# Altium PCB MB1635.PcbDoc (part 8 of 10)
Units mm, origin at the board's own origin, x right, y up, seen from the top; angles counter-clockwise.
Board outline 127 x 97 mm, 6 copper layers (Top Layer, Signal Layer 1, Signal Layer 2, Signal Layer 3, Signal Layer 4, Bottom Layer), stack 1.557 mm thick; 593 components, 478 nets, 2435 pads, 1743 vias.
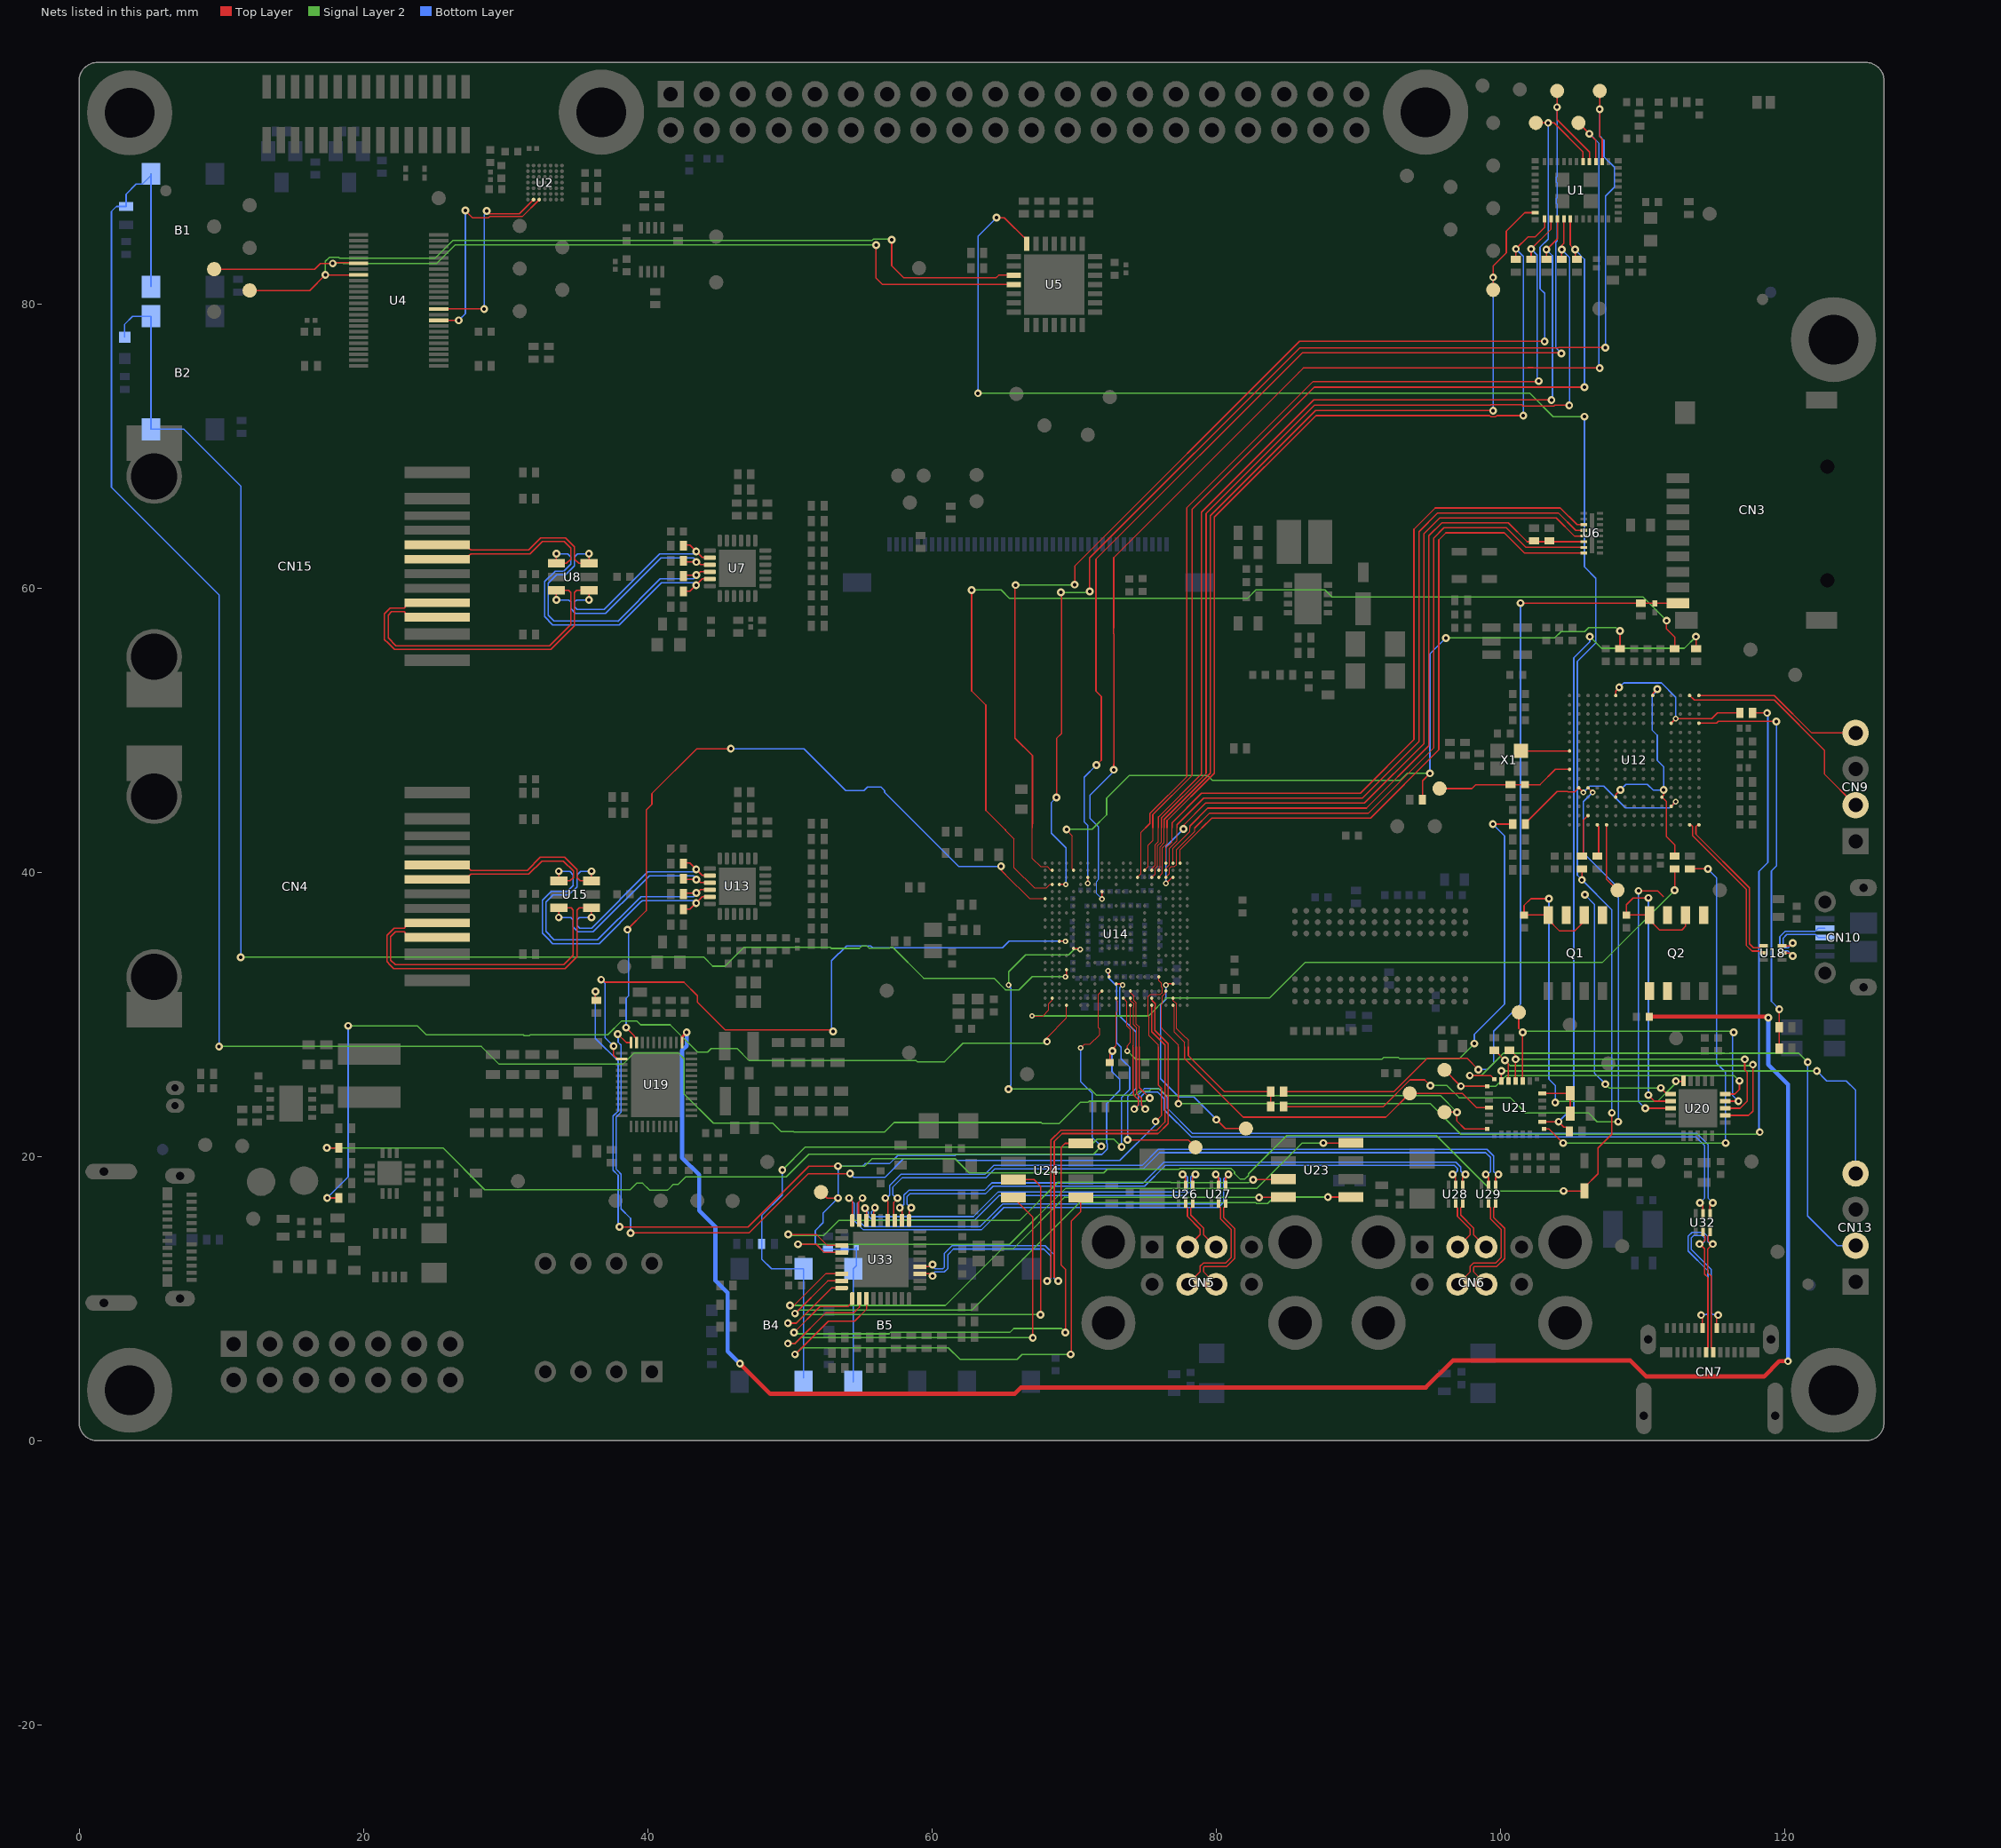
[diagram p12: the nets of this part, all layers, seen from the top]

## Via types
v1: diameter 0.55, hole 0.25, Top Layer to Bottom Layer, 1438 vias
v2: diameter 0.4, hole 0.2, Top Layer to Bottom Layer, 276 vias
v3: diameter 0.26, hole 0.1, Top Layer to Signal Layer 1, tented both sides, 29 vias

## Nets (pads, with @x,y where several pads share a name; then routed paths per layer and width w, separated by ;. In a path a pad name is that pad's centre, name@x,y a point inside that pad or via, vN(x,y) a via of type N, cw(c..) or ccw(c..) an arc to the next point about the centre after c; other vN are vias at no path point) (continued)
NetU2_E7: U2.E7 U4.33 | length 15.3
  Top Layer w0.1: U4.33@25.3,78.85 v1(26.7,78.85) ; v1(27.175,86.575) 27.675,86.075 28.801,86.075 28.876,86.15 31.175,86.15 U2.E7@32.375,87.35
  Bottom Layer w0.1: v1(26.7,78.85) 27.175,79.325 v1(27.175,86.575)
NetU2_F7: U2.F7 U4.35 | length 14
  Top Layer w0.1: U4.35@25.3,79.65 25.304,79.654 v1(28.501,79.654) ; v1(28.675,86.55) 28.875,86.35 30.975,86.35 U2.F7@31.975,87.35
  Bottom Layer w0.1: v1(28.501,79.654) 28.501,85.876 28.501,86.266 28.675,86.44 v1(28.675,86.55)
NetU12_G1: U12.G1 X1.3 | length 3.4
  Top Layer w0.1: X1.3@101.45,48.55 U12.G1@104.875,48.55
notOC1: U23.8 U33.13 | length 45.2
  Top Layer w0.1: v1(50.575,13.825) 51.875,13.825 52.45,13.25 U33.13@53.65,13.25 ; v1(87.55,20.95) 89.47,20.95 U23.8@89.475,20.955
  Signal Layer 2 w0.1: v1(50.575,13.825) 65.475,13.825 69.4,17.75 82.85,17.75 86.05,20.95 v1(87.55,20.95)
notOC2: U23.5 U33.17 | length 46.8
  Top Layer w0.1: v1(50.375,8.95) 52.675,11.25 U33.17@53.65,11.25 ; v1(87.875,17.15) 89.47,17.15 U23.5@89.475,17.145
  Signal Layer 2 w0.1: v1(50.375,8.95) 50.625,9.2 62.825,9.2 70.375,16.75 82.804,16.75 82.853,16.701 83.626,16.701 84.075,17.15 v1(87.875,17.15)
notOC3: U24.8 U33.19 | length 39.3
  Top Layer w0.1: v1(50.3,7.625) 52.125,9.45 54.1,9.45 54.4,9.75 U33.19@54.4,10 ; v1(69.4,7.625) 69.4,12.075 69.1,12.375 69.1,20.65 69.38,20.93 U24.8@70.475,20.93
  Signal Layer 2 w0.1: v1(50.3,7.625) 50.386,7.539 50.57,7.539 50.584,7.525 56.987,7.525 57.087,7.625 65.492,7.625 65.767,7.9 69.125,7.9 v1(69.4,7.625)
notOC4: U24.5 U33.21 | length 38.5
  Top Layer w0.1: v1(50.375,6.075) 52.725,8.425 54.575,8.425 55.4,9.25 U33.21@55.4,10 ; v1(69.775,6.075) 69.825,6.125 69.825,15.475 70.475,16.125 U24.5@70.475,17.12
  Signal Layer 2 w0.1: v1(50.375,6.075) 50.85,6.55 61.166,6.55 61.991,5.725 65.997,5.725 66.347,6.075 v1(69.775,6.075)
NRST: B5.1 B5.2 C118.1 C223.2 D4.2 R88.2 R114.1 R180.1 TP29.1 U5.14 U14.Y11 U37.1 | length 261.7
  Top Layer w0.075: 72.875,27.725 72.982,27.832 72.982,30.151 73.059,30.229 73.059,30.923 72.999,30.983 72.999,31.126 U14.Y11@72.975,31.15
  Top Layer w0.1: v1(36.325,31.625) 36.325,31.075 R114.1@36.4,31 ; v1(38.025,15.05) 47.075,15.05 51.35,19.325 v1(53.4,19.325) ; TP29.1@52.2,17.5 52.625,17.075 v1(53.4,17.075) ; v1(64.55,86.075) 65.1,86.075 66.675,84.5 U5.14@66.675,84.225 ; C118.1@72.525,26.625 72.525,27.325 72.626,27.426 v1(72.703,27.426) ; v1@72.675,27.525 72.875,27.725 ; v1(104.45,17.575) 105.92,17.575 105.92,17.845 106.875,18.8 106.875,20.6 107.85,21.575 v1(107.85,23.075) ; v1(105.75,39.475) R88.2@105.75,40.25
  Signal Layer 2 w0.1: v1(53.4,19.325) 55.275,19.325 55.8,19.85 61.625,19.85 62.625,18.85 72.1,18.85 72.35,19.1 77.399,19.1 77.474,19.175 81.051,19.175 81.3,18.926 81.3,18.804 81.678,18.426 82.03,18.426 82.279,18.675 82.279,18.784 84.97,21.475 95.5,21.475 99.4,17.575 v1(104.45,17.575) ; v1(63.25,73.725) 102.075,73.725 103.725,72.075 v1(105.925,72.075)
  Bottom Layer w0.1: v1(36.325,31.625) 36.325,28.325 37.925,26.725 37.925,23.2 ; 37.925,23.75 37.925,23.2 ; v1(38.025,15.05) 37.939,15.136 37.939,15.32 37.925,15.334 37.925,18.685 37.575,19.035 37.575,22.85 37.925,23.2 ; B5.2@54.475,4.15 B5.1@54.475,12.1 54.692,12.317 U37.1@54.692,13.602 ; U37.1@54.692,13.625 U37.1@54.692,13.602 ; v1(63.25,73.725) 63.25,84.775 v1(64.55,86.075) ; v1@72.675,27.525 72.675,25.975 73.225,25.425 73.225,24.658 72.3,23.733 72.3,20.951 72.35,20.901 72.35,20.549 72.3,20.499 72.3,20.475 71.975,20.15 61.725,20.15 61.65,20.075 57.6,20.075 57.025,19.5 55.3,19.5 55.125,19.325 v1(53.4,19.325) v1(53.4,17.075) 52.349,16.024 52.349,15.349 51.8,14.8 51.8,13.9 52.213,13.487 R180.1@52.692,13.487 C223.2@53.867,13.487 54.577,13.487 U37.1@54.692,13.602 ; v1(105.925,72.075) 105.925,61.5 106.725,60.7 106.725,56.15 105.422,54.847 105.422,39.803 v1(105.75,39.475) 107.85,37.375 v1(107.85,23.075)
PA13: B2.1 B2.2 LD4.2 U14.T4 | length 113.2
  Top Layer w0.09: v2@69.475,32.725 U14.T4@69.475,33.15
  Signal Layer 2 w0.09: 65.175,31.75 65.2,31.725 66.125,31.725 67.05,32.65 v2(69.4,32.65)
  Signal Layer 2 w0.1: v1(11.375,34.025) 11.4,34.05 43.934,34.05 44.584,33.4 45.449,33.4 46.774,34.725 52.849,34.725 52.924,34.65 54.9,34.65 55.077,34.827 55.429,34.827 55.579,34.677 57.029,34.677 57.077,34.725 57.25,34.725 59.425,32.55 64.375,32.55 65.175,31.75
  Bottom Layer w0.1: LD4.2@3.205,77.663 3.205,78.58 3.763,79.138 B2.1@5.055,79.138 B2.2@5.055,71.188 7.372,71.188 11.375,67.185 v1(11.375,34.025)
PA14: B1.1 B1.2 LD3.2 U14.W13 | length 153.4
  Top Layer w0.075: U14.W13@73.975,31.65 73.998,31.627 73.998,31.502 74.225,31.275 74.225,30.987 74.39,30.822 74.39,29.335 74.595,29.13 74.595,27.725
  Top Layer w0.1: 74.595,27.725 74.595,27.269 74.595,24.855 v1(75.325,24.125)
  Signal Layer 2 w0.1: v1(9.85,27.75) 28.3,27.75 29.55,26.5 38.275,26.5 39.075,27.3 42.151,27.3 42.575,26.876 42.575,24.401 44.626,22.35 48.804,22.35 49.404,21.75 50.284,21.75 50.309,21.725 56.675,21.725 57.35,22.4 67.7,22.4 67.775,22.325 68.95,22.325 70.451,23.826 70.979,23.826 71.053,23.9 75.041,23.9 75.266,24.125 v1(75.325,24.125)
  Bottom Layer w0.1: B1.2@5.055,81.213 B1.1@5.055,89.038 ; B1.1@5.055,89.163 B1.1@5.055,89.038 ; v1(9.85,27.75) 9.85,59.525 2.275,67.1 2.275,86.517 2.621,86.863 LD3.2@3.305,86.863 3.305,87.73 4.013,88.438 4.455,88.438 B1.1@5.055,89.038
PF8_WKUP: U14.F1 U19.43 | length 52.5
  Top Layer w0.075: 65.175,39.85 66.875,38.15 U14.F1@67.975,38.15
  Top Layer w0.1: v1(38.487,29.075) 39.075,28.487 39.075,28.424 39.149,28.35 39.212,28.35 39.225,28.337 U19.43@39.225,28.025 ; v1(38.575,35.975) 39.9,37.3 39.9,44.383 40.3,44.783 40.3,45.55 43.452,48.702 v1(45.852,48.702) ; v1(64.875,40.425) 64.875,40.15 65.175,39.85
  Bottom Layer w0.1: v1(38.487,29.075) 38.487,31.137 38.65,31.3 38.65,35.9 v1(38.575,35.975) ; v1(45.852,48.702) 50.998,48.702 53.95,45.75 55.225,45.75 55.475,46 56.426,46 56.675,45.751 56.675,45.625 61.875,40.425 v1(64.875,40.425)
PH4: R188.2 R189.2 U14.Y19 | length 12.4
  Top Layer w0.075: U14.Y19@76.975,31.15 76.986,31.139 76.986,30.989 77.225,30.75 77.225,30.296 77.225,29.025 77.638,28.613 78.05,28.2 78.05,27.725
  Top Layer w0.1: 78.05,27.725 78.05,27.1 80.582,24.568 R188.2@83.85,24.568 R189.2@83.85,23.518
PMIC_WAKEUP: U14.M3 U19.2 | length 47.1
  Top Layer w0.09: v1(37.6,27.775) 37.6,27.145 37.87,26.875 U19.2@38.175,26.875 ; U14.M3@68.975,35.15 v2(69.4,35.15) v2@69.425,35.15
  Top Layer w0.1: v1(36.725,32.45) 36.834,32.45 37.009,32.275 42.551,32.275 43.5,31.326 43.5,30.875 45.45,28.925 52.925,28.925 v1(53.05,28.8)
  Bottom Layer w0.09: 52.95,33.725 52.95,33.775 53.997,34.822 55.703,34.822 55.843,34.682 64.985,34.682 65.175,34.872 65.453,35.15 v2(69.4,35.15)
  Bottom Layer w0.1: v1(36.725,32.45) 37,32.175 37,28.375 v1(37.6,27.775) ; 52.95,33.725 52.95,29.084 52.964,29.07 52.964,28.886 v1(53.05,28.8)
PRTPWR1: U23.3 U33.12 | length 40.6
  Top Layer w0.1: v1(49.9,14.525) 49.925,14.5 51.9,14.5 52.65,13.75 U33.12@53.65,13.75 ; v1(82.604,18.376) 84.666,18.376 84.715,18.425 U23.3@84.725,18.415
  Signal Layer 2 w0.1: v1(49.9,14.525) 49.975,14.45 52.4,14.45 53.45,15.5 66.175,15.5 68.875,18.2 76.778,18.2 76.803,18.176 82.326,18.176 82.526,18.376 v1(82.604,18.376)
PRTPWR2: U23.4 U33.16 | length 42.4
  Top Layer w0.1: v1(50.025,9.525) 50.3,9.525 52.525,11.75 U33.16@53.65,11.75 ; v1(83.029,17.126) 84.696,17.126 84.72,17.15 U23.4@84.725,17.145
  Signal Layer 2 w0.1: v1(50.025,9.525) 60.95,9.525 64.925,13.5 65.7,13.5 69.35,17.15 69.374,17.126 v1(83.029,17.126)
PRTPWR3: U24.3 U33.18 | length 34
  Top Layer w0.1: v1(49.875,8.275) 50.475,8.275 52.95,10.75 U33.18@53.65,10.75 ; U24.3@65.725,18.39 67.185,18.39 67.65,17.925 v1(67.65,8.875)
  Signal Layer 2 w0.1: v1(49.875,8.275) 50.425,8.275 51.025,8.875 v1(67.65,8.875)
PRTPWR4: U24.4 U33.20 | length 34.5
  Top Layer w0.1: v1(49.875,6.85) 50.375,6.85 52.525,9 54.5,9 54.9,9.4 U33.20@54.9,10 ; U24.4@65.725,17.12 67.1,15.745 v1(67.1,7.25)
  Signal Layer 2 w0.1: v1(49.875,6.85) 50.375,6.85 50.775,7.25 v1(67.1,7.25)
PWR_LP: TP61.1 U14.V19 | length 15
  Top Layer w0.09: v2@76.55,32.15 U14.V19@76.975,32.15
  Top Layer w0.1: v1(80.025,22.6) 80.65,21.975 TP61.1@82.1,21.975 TP61.1@82.475,21.975
  Bottom Layer w0.09: 76.1,27.725 76.1,30.7 76.475,31.075 v2(76.475,32.075)
  Bottom Layer w0.1: 76.1,27.725 76.1,25.47 77.379,24.191 78.434,24.191 v1(80.025,22.6)
PWR_NJTRST: TP63.1 U14.V11 | length 17.5
  Top Layer w0.1: U14.V11@72.975,32.15 v2@73.4,32.15 ; v1(73.775,21.175) 78.025,21.175 TP63.1@78.55,20.65 TP63.1@78.55,20.3
  Bottom Layer w0.09: v2(73.425,32.075) 73.225,31.875 73.225,29.9 74.375,28.75 74.375,27.725
  Bottom Layer w0.1: v1(73.775,21.175) 73.775,24.2 74.375,24.8 74.375,27.725
PWR_ON: U14.U17 U19.44 | length 68.4
  Top Layer w0.075: 75.95,27.725 75.95,27.85 75.284,28.516 75.284,29.816 75.221,29.879 75.221,31.246 75.378,31.403 76.076,31.403 76.225,31.552 76.225,31.856 76.144,31.938 76.144,32.206 75.974,32.376 U14.U17@75.974,32.65
  Top Layer w0.1: v1(37.9,28.625) 38.5,28.025 U19.44@38.825,28.025 ; v1(38.8,14.625) 47.125,14.625 51.3,18.8 v1(54.25,18.8) ; v1(75.75,22.475) 76.15,22.875 76.15,24.816 75.95,25.016 75.95,27.725
  Bottom Layer w0.1: v1(37.9,28.625) 37.925,28.6 37.925,28.051 38.125,27.851 38.125,23.4 ; 38.125,23.165 38.125,23.117 ; 38.125,23.579 38.125,23.4 ; v1(38.8,14.625) 38.8,15.65 38.125,16.325 38.125,18.768 37.891,19.002 37.775,19.118 37.775,22.767 38.125,23.117 ; v1(54.25,18.8) 54.5,18.55 56.7,18.55 58,19.85 61.625,19.85 61.75,19.725 73.225,19.725 75.75,22.25 v1(75.75,22.475) ; 38.125,23.117 38.125,23.4
PWR_ON_DB: C102.2 Q2.5 Q2.6 U19.35 | length 135.7
  Top Layer w0.2: U19.35@42.425,28.025 42.425,28.425 v1(42.75,28.75)
  Top Layer w0.3: v1(46.5,5.425) 48.625,3.3 65.825,3.3 66.275,3.75 94.763,3.75 96.663,5.65 107.16,5.65 109.15,5.65 110.275,4.525 118.55,4.525 119.625,5.6 v1(120.244,5.6) ; C102.2@110.475,29.85 118.707,29.85 118.782,29.775 v1(118.85,29.775)
  Bottom Layer w0.3: v1(42.75,28.75) 42.75,27.801 42.425,27.476 42.425,19.925 43.625,18.725 43.625,16.2 44.775,15.05 44.775,11.275 45.625,10.425 45.625,6.3 v1(46.5,5.425) ; v1(118.85,29.775) 118.85,26.475 120.244,25.081 v1(120.244,5.6)
RD1_N: CN4.8 R97.1 U13.22 U15.6 | length 34
  Top Layer w0.09: CN4.8@25.2,40.53 27.195,40.53 27.58,40.145 29.93,40.145 31.531,40.145 32.446,41.06 34.169,41.06 35.025,40.204 35.025,39.625 35.25,39.4 U15.6@36.05,39.4 v1(36.05,40.075) ; R97.1@42.525,38.475 42.6,38.55 v1(43.425,38.55) 43.5,38.55 43.725,38.775 U13.22@44.375,38.775
  Bottom Layer w0.09: v1(36.05,40.075) 35.275,40.075 35.025,39.825 35.025,39.218 35.035,39.208 35.035,38.992 34.443,38.4 33.339,38.4 32.864,37.925 32.85,37.925 32.85,35.839 33.425,35.264 33.425,35.25 36.486,35.25 39.444,38.208 39.458,38.208 39.531,38.281 43.231,38.281 43.425,38.475 v1(43.425,38.55)
RD1_P: CN4.7 R99.1 U13.23 U15.1 | length 34.1
  Top Layer w0.09: CN4.7@25.2,39.51 27.195,39.51 27.57,39.885 29.822,39.885 31.639,39.885 32.554,40.8 34.075,40.8 34.775,40.1 34.775,39.625 34.55,39.4 U15.1@33.75,39.4 v1(33.75,40.075) ; R99.1@42.525,37.4 42.975,37.4 v1(43.413,37.838) 43.85,38.275 U13.23@44.375,38.275
  Bottom Layer w0.09: v1(33.75,40.075) 34.525,40.075 34.765,39.835 34.765,39.11 34.775,39.1 34.335,38.66 33.231,38.66 32.756,38.185 32.742,38.185 32.59,38.033 32.59,35.731 33.165,35.156 33.165,35.142 33.317,34.99 36.594,34.99 39.552,37.948 39.566,37.948 39.639,38.021 43.229,38.021 v1(43.413,37.838)
RD2_N: CN15.8 R40.1 U7.22 U8.6 | length 33.5
  Top Layer w0.09: CN15.8@25.2,63.06 27.195,63.06 27.455,62.8 27.455,62.795 27.565,62.685 31.621,62.685 32.486,63.55 34.229,63.55 34.85,62.929 34.85,62.05 35.15,61.75 U8.6@35.875,61.75 v1(35.875,62.425) ; R40.1@42.525,60.85 42.6,60.925 v1(43.425,60.925) 43.5,60.925 43.725,61.15 U7.22@44.375,61.15
  Bottom Layer w0.09: v1(35.875,62.425) 35.075,62.425 34.86,62.21 34.86,61.581 34.385,61.106 34.385,61.092 34.233,60.94 33.61,60.94 33.6,60.95 33.01,60.36 33.01,58.11 33,58.1 33.415,57.685 37.89,57.685 37.9,57.675 40.881,60.656 43.231,60.656 43.425,60.85 v1(43.425,60.925)
RD2_P: CN15.7 R42.1 U7.23 U8.1 | length 33.6
  Top Layer w0.09: CN15.7@25.2,62.04 27.195,62.04 27.455,62.3 27.455,62.305 27.575,62.425 31.729,62.425 32.604,63.3 34.125,63.3 34.225,63.2 34.6,62.825 34.6,62.05 34.3,61.75 U8.1@33.575,61.75 v1(33.575,62.425) ; R42.1@42.525,59.775 42.975,59.775 v1(43.413,60.213) 43.85,60.65 U7.23@44.375,60.65
  Bottom Layer w0.09: v1(33.575,62.425) 34.375,62.425 34.6,62.2 34.6,61.689 34.125,61.214 34.125,61.2 33.718,61.2 33.708,61.21 33.492,61.21 32.75,60.468 32.75,58.218 32.74,58.208 32.74,57.992 33.307,57.425 37.782,57.425 37.792,57.415 38.008,57.415 40.989,60.396 43.229,60.396 v1(43.413,60.213)
SDMMC1_CK: R33.2 R34.1 U6.6 U14.A19 | length 48.9
  Top Layer w0.075: U14.A19@76.975,40.65 76.975,41.7 78.15,42.875 78.15,43.125
  Top Layer w0.1: 78.15,43.125 78.15,43.265 79.41,44.525 90.585,44.525 94.975,48.915 94.975,63.69 95.885,64.6 100.565,64.6 101.89,63.275 102.375,63.275 103.45,63.275 U6.6@105.875,63.275
SDMMC1_CMD: U6.5 U14.C19 | length 51.8
  Top Layer w0.09: v1(77.7,43.05) v1@77.7,43.125
  Top Layer w0.1: v2(76.475,39.225) 76.875,39.625 76.95,39.625 76.975,39.65 U14.C19@76.975,39.638 ; v1@77.7,43.125 77.7,43.31 79.265,44.875 90.275,44.875 ; U6.5@105.875,63.675 105.21,63.675 103.935,64.95 95.74,64.95 94.625,63.835 94.625,49.06 90.44,44.875 ; 90.275,44.875 90.44,44.875 ; 90.275,44.875 90.44,44.875
  Bottom Layer w0.09: v2(76.475,39.225) 76.475,41.825 v1(77.7,43.05)
SDMMC1_D0: U6.7 U14.C18 | length 49.8
  Top Layer w0.075: U14.C18@76.475,39.65 76.725,39.9 76.725,40.275 76.85,40.4 77.079,40.4 77.225,40.546 77.225,41.605 78.505,42.885 78.505,43.125
  Top Layer w0.1: 78.505,43.125 79.555,44.175 90.73,44.175 95.325,48.77 95.325,63.545 96.03,64.25 100.42,64.25 101.795,62.875 U6.7@105.875,62.875
SDMMC1_D1: U6.8 U14.A20 | length 47.8
  Top Layer w0.075: U14.A20@77.475,40.65 77.475,41.6 79,43.125
  Top Layer w0.1: 79,43.125 79.7,43.825 90.875,43.825 95.675,48.625 95.675,63.4 96.175,63.9 100.275,63.9 101.7,62.475 U6.8@105.875,62.475
SDMMC1_D2: U6.3 U14.A18 | length 50.3
  Top Layer w0.075: U14.A18@76.475,40.65 76.475,41.716 76.9,42.141 76.9,43.125
  Top Layer w0.1: 76.9,43.125 76.9,43.5 78.975,45.575 90.15,45.575 93.925,49.35 93.925,64.15 95.425,65.65 104.225,65.65 105.4,64.475 U6.3@105.875,64.475
SDMMC1_D3: U6.4 U14.B18 | length 50.4
  Top Layer w0.075: U14.B18@76.475,40.15 76.475,40.296 76.725,40.546 76.725,41.705 77.25,42.23 77.25,43.125
  Top Layer w0.1: 77.25,43.125 77.25,43.355 79.12,45.225 90.295,45.225 94.275,49.205 94.275,63.98 95.595,65.3 104.08,65.3 105.305,64.075 U6.4@105.875,64.075
SDMMC2_CK: TP27.1 U1.20 U14.B17 | length 65.9
  Top Layer w0.075: U14.B17@75.975,40.15 75.987,40.162 75.987,40.309 76.059,40.381 76.059,41.798 76.35,42.089 76.35,43.125
  Top Layer w0.1: 76.35,43.125 76.35,43.733 79.6,46.983 79.6,65.1 87,72.5 v1(99.5,72.5) ; TP27.1@99.5,81 v1(99.5,81.875) 99.5,82.675 100.425,83.6 100.425,85.125 101.725,86.425 U1.20@102.45,86.425
  Bottom Layer w0.1: v1(99.5,72.5) v1(99.5,81.875)
SDMMC2_CMD: R14.2 U1.22 U14.C17 | length 67.6
  Top Layer w0.075: U14.C17@75.975,39.65 75.975,39.678 76.228,39.931 76.228,40.311 76.228,41.728 76.55,42.05 76.55,42.35 76.55,43.125
  Top Layer w0.1: 76.55,43.125 76.55,43.65 79.875,46.975 79.875,65 87.025,72.15 99.249,72.15 99.324,72.075 99.676,72.075 99.751,72.15 v1(101.625,72.15) ; R14.2@101.1,83.15 v1(101.1,83.875) 101.95,84.725 102.45,84.725 103.125,85.4 U1.22@103.125,85.975
  Bottom Layer w0.1: v1(101.1,83.875) 101.625,83.35 v1(101.625,72.15)
SDMMC2_D0: R16.2 U1.24 U14.B16 | length 68.5
  Top Layer w0.075: U14.B16@75.475,40.15 75.498,40.173 75.498,40.298 75.721,40.521 75.721,41.521 75.721,41.938 75.95,42.167 75.95,43.125
  Top Layer w0.1: 75.95,43.125 75.95,43.9 78.975,46.925 78.975,65.35 86.875,73.25 v1(103.6,73.25) ; R16.2@103.25,83.15 v1(103.25,83.825) 104.025,84.6 U1.24@104.025,85.975
  Bottom Layer w0.1: v1(103.25,83.825) 103.675,83.4 103.675,73.325 v1(103.6,73.25)
SDMMC2_D1: R18.2 U1.26 U14.B15 | length 71
  Top Layer w0.075: U14.B15@74.975,40.15 75.225,40.4 75.225,41.025 75.225,41.92 75.557,42.252 75.557,43.118 75.55,43.125
  Top Layer w0.1: 75.55,43.125 75.55,44.066 78.325,46.841 78.325,65.575 86.9,74.15 v1(105.925,74.15) ; U1.26@104.925,85.975 104.925,84.15 105.25,83.825 v1(105.275,83.825) 105.275,83.275 R18.2@105.4,83.15
  Bottom Layer w0.1: v1(105.275,83.825) 105.275,83.8 105.925,83.15 v1(105.925,74.15)
SDMMC2_D2: R15.2 U1.23 U14.C14 | length 68.8
  Top Layer w0.075: U14.C14@74.475,39.65 74.725,39.9 74.725,42.817 75.038,43.13
  Top Layer w0.1: 75.038,43.13 75.35,43.442 75.35,44.149 77.95,46.749 77.95,65.675 86.825,74.55 102.675,74.55 v1(102.7,74.575) ; R15.2@102.175,83.15 v1(102.175,83.875) 103.575,85.275 U1.23@103.575,85.975
  Bottom Layer w0.1: v1(102.175,83.875) 102.6,83.45 102.6,74.797 102.7,74.697 v1(102.7,74.575)
SDMMC2_D3: R17.2 U1.25 U14.C16 | length 70.1
  Top Layer w0.075: U14.C16@75.475,39.65 75.721,39.896 75.721,40.282 75.89,40.451 75.89,41.69 75.89,41.868 76.15,42.128 76.15,43.125
  Top Layer w0.1: 76.15,43.125 76.15,43.816 79.3,46.966 79.3,65.25 86.925,72.875 99.274,72.875 99.324,72.925 101.5,72.925 101.6,72.825 103.776,72.825 103.826,72.875 v1(104.85,72.875) ; R17.2@104.325,83.15 v1(104.325,83.825) 104.325,84.125 104.475,84.275 U1.25@104.475,85.975
  Bottom Layer w0.1: v1(104.325,83.825) 104.875,83.275 104.875,72.9 v1(104.85,72.875)
SNK_GDCG: C87.1 Q2.2 Q2.4 U20.7 | length 23.8
  Top Layer w0.1: v1(110.425,24.325) 110.85,23.9 U20.7@111.975,23.9 ; v1(110.425,38.2) 109.35,38.2 108.875,37.725 C87.1@108.875,37 Q2.4@110.495,37 110.495,36.655 111.2,35.95 112.775,35.95 113.035,36.21 Q2.2@113.035,37
  Bottom Layer w0.1: v1(110.425,24.325) v1(110.425,38.2)
SNK_GDCS: Q2.1 Q2.3 U20.8 | length 19.2
  Top Layer w0.1: v1(109.725,38.7) 111.075,38.7 111.475,38.3 ; v1(110.2,23.4) U20.8@111.975,23.4
  Bottom Layer w0.1: v1(109.725,38.7) 109.725,23.875 v1(110.2,23.4)
SRC_GDCG: C86.1 Q1.2 Q1.4 U20.5 | length 32.5
  Top Layer w0.1: v1(103.425,38.15) 102.15,38.15 101.675,37.675 C86.1@101.675,37 Q1.4@103.37,37 103.37,36.68 104.175,35.875 105.225,35.875 105.91,36.56 Q1.2@105.91,37 ; v1(112.35,25.3) 112.875,25.3 U20.5@112.9,25.325
  Signal Layer 2 w0.1: v1(103.875,23.8) 103.95,23.875 111.05,23.875 112.212,25.037 112.212,25.04 112.35,25.178 v1(112.35,25.3)
  Bottom Layer w0.1: v1(103.425,38.15) 103.425,25.45 103.875,25 v1(103.875,23.8)
SRC_GDCS: Q1.1 Q1.3 U20.6 | length 18.8
  Top Layer w0.1: v1(111.3,24.825) 111.725,24.4 U20.6@111.975,24.4
  Signal Layer 2 w0.1: v1(107.4,25.1) 107.675,24.825 v1(111.3,24.825)
  Bottom Layer w0.1: v1(105.95,38.425) 106.625,37.75 106.625,25.875 v1(107.4,25.1)
STLINK_SWCLK: R90.2 U14.Y2 | length 52.7
  Top Layer w0.075: v2(67.05,29.9) 67.8,29.9 68.225,30.325 68.225,30.76 68.475,31.01 U14.Y2@68.475,31.15
  Top Layer w0.1: v1(112.275,38.75) R90.2@112.275,40.25
  Signal Layer 2 w0.1: v2(67.05,29.9) 75.25,29.9 76.525,31.175 81.275,31.175 83.775,31.175 86.275,33.675 107.2,33.675 v1(112.275,38.75)
STLINK_SWDIO: R81.2 U14.Y12 | length 47.3
  Top Layer w0.075: U14.Y12@73.475,31.15 73.725,30.9 73.725,29.194 73.982,28.938 73.982,28.032 73.75,27.8 73.75,27.725
  Top Layer w0.1: v2(73.75,27.425) 73.75,27.725 ; v1(99.475,43.4) R81.2@100.875,43.4
  Signal Layer 2 w0.1: v2(73.75,27.425) 73.775,27.425 74.35,26.85 91.674,26.85 91.799,26.975 92.826,26.975 92.926,26.875 97.1,26.875 v1(98.175,27.95)
  Bottom Layer w0.1: v1(98.175,27.95) 98.175,28.6 100.3,30.725 100.3,42.575 v1(99.475,43.4)
STLINK_SWO: R61.2 U14.W18 | length 81.2
  Top Layer w0.075: 76.213,28.988 76.144,29.058 76.144,30.744 76.225,30.825 76.225,31.3 76.445,31.52 76.445,31.62 U14.W18@76.474,31.65 ; 76.214,28.989 77.35,27.853 77.35,27.725
  Top Layer w0.1: v1(77.35,23.725) 77.35,27.725 ; R61.2@117.75,51.225 v1(118.775,51.225)
  Signal Layer 2 w0.1: v1(77.35,23.725) 95.075,23.725 97.225,21.575 117.978,21.575 118.128,21.725 v1(118.25,21.725)
  Bottom Layer w0.1: v1(118.25,21.725) 118.2,21.775 118.2,40.075 118.825,40.7 118.825,51.175 v1(118.775,51.225)
STLK_LED: R117.2 R125.2 U12.D15 | length 28.9
  Top Layer w0.1: U12.D15@113.975,50.5 115.225,50.5 115.35,50.625 v1(119.425,50.625) ; R125.2@119.625,27.6 R117.2@119.625,29.1 v1(119.625,30.375)
  Bottom Layer w0.1: v1(119.425,50.625) 119.425,40.45 119.075,40.1 119.075,30.925 v1(119.625,30.375)
STLK_RST: C65.2 R68.1 TP44.1 U12.J1 | length 9.7
  Top Layer w0.1: TP44.1@95.725,45.9 98,45.9 98.275,46.175 99.65,46.175 R68.1@100.725,46.175 C65.2@101.725,46.175 102.8,46.175 103.875,47.25 U12.J1@104.875,47.25
STLK_SWCLK: CN9.2 U12.A14 | length 15.9
  Top Layer w0.1: U12.A14@113.325,52.45 113.65,52.125 119.275,52.125 122.8,48.6 122.8,46.93 CN9.2@125,44.73
STLK_SWDIO: CN9.4 U12.A15 | length 12.1
  Top Layer w0.1: U12.A15@113.975,52.45 119.275,52.45 121.915,49.81 CN9.4@125,49.81
STLK_VCP2_RX: R91.1 U21.8 | length 34.3
  Top Layer w0.1: U21.8@103.075,21.95 103.425,21.95 v1(104.425,20.95) ; R91.1@113.35,40.25 v1(114.6,40.25)
  Signal Layer 2 w0.1: v1(104.425,20.95) v1(115.85,20.95)
  Bottom Layer w0.1: v1(114.6,40.25) 115.225,39.625 115.225,26.575 115.85,25.95 v1(115.85,20.95)
STLK_VCP2_TX: R56.1 R187.1 U21.9 | length 46.3
  Top Layer w0.1: U21.9@102.95,22.45 v1(104.1,22.45) 104.475,22.075 104.645,22.075 104.85,21.87 R187.1@104.85,21.775 ; R56.1@113.775,55.75 v1(113.775,56.6)
  Signal Layer 2 w0.1: v1(106.3,56.6) 107.125,55.775 112.95,55.775 v1(113.775,56.6)
  Bottom Layer w0.1: v1(104.1,22.45) 105.175,23.525 105.175,55.1 106.3,56.225 v1(106.3,56.6)
STM32G0_I2C2_SCL: R121.2 U20.18 U21.18 | length 23.3
  Top Layer w0.1: R121.2@100.65,27.475 100.725,27.475 101.075,27.125 v1(101.075,26.85) U21.18@101.075,25.325 ; U20.18@115.825,23.4 116.875,23.4 117.375,23.9 117.375,25.925 117.2,26.1 v1(117.2,26.85)
  Signal Layer 2 w0.1: v1(101.075,26.85) v1(117.2,26.85)
STM32G0_I2C2_SDA: R120.1 U20.17 U21.19 | length 25.6
  Top Layer w0.1: R120.1@99.575,27.475 99.625,27.475 v1(100.325,26.775) 100.575,26.525 U21.19@100.575,25.325 ; U20.17@115.825,22.9 117.475,22.9 117.775,23.2 v1(117.775,26.475)
  Signal Layer 2 w0.1: v1(100.325,26.775) 100.7,26.4 117.7,26.4 v1(117.775,26.475)
STM32G0_INTN: TP59.1 U14.N5 U21.28 | length 51
  Top Layer w0.09: U14.N5@69.975,34.65 70.002,34.623 70.397,34.623 v2(70.442,34.578)
  Top Layer w0.1: TP59.1@96.075,23.125 v1(96.95,23.125) 96.95,22.5 97.5,21.95 U21.28@99.075,21.95
  Signal Layer 2 w0.09: v2(65.4,32.075) 65.4,33 66.6,34.2 69.625,34.2 70.003,34.578 v2(70.442,34.578)
  Signal Layer 2 w0.1: v1(65.4,24.75) 71.155,24.75 71.58,24.325 74.3,24.325 74.585,24.61 75.28,24.61 75.42,24.75 76.075,24.75 76.525,24.3 95.775,24.3 v1(96.95,23.125)
  Bottom Layer w0.09: v2(65.4,32.075) 65.4,32.031 65.57,31.861 65.57,27.725
  Bottom Layer w0.1: v1(65.4,24.75) 65.4,24.869 65.57,25.039 65.57,27.725
STM32G0_SWCLK: CN13.2 U21.21 | length 41.6
  Top Layer w0.1: v1(97.85,25.7) 99.325,25.7 U21.21@99.575,25.45
  Signal Layer 2 w0.1: v1(97.85,25.7) 98.65,25.7 99.9,26.95 ; 99.9,26.951 100.224,27.275 115.78,27.275 115.805,27.25 116.095,27.25 116.12,27.275 121,27.275 v1(121.625,26.65)
  Bottom Layer w0.1: v1(121.625,26.65) 121.625,15.825 123.72,13.73 CN13.2@125,13.73
STM32G0_SWDIO: CN13.4 U21.20 | length 32.1
  Top Layer w0.1: U21.20@100.075,25.325 v1(100.075,26.025)
  Signal Layer 2 w0.1: v1(100.075,26.025) v1(122.275,26.025)
  Bottom Layer w0.1: v1(122.275,26.025) 122.975,25.325 124.351,25.325 125,24.676 CN13.4@125,18.81
STM32G0_WAKE: TP58.1 U14.AA19 U21.25 | length 28.3
  Top Layer w0.075: U14.AA19@76.974,30.65 76.974,30.61 77.056,30.528 77.056,30.465 77.056,28.769 77.638,28.188 77.775,28.05 77.775,27.725
  Top Layer w0.1: 77.775,27.725 77.775,26.9 81.9,22.775 91.95,22.775 TP58.1@93.625,24.45 97.325,24.45 98.325,23.45 U21.25@99.2,23.45
STMIPI_ERROR: TP25.1 U4.6 U5.18 | length 61.5
  Top Layer w0.1: TP25.1@9.5,82.45 16.575,82.45 16.975,82.85 v1@17.975,82.85 ; v1(17.85,82.85) 17.9,82.9 19.6,82.9 U4.6@19.65,82.85 ; v1(56.075,84.15) 56.075,81.825 56.525,81.375 U5.18@65.775,81.375
  Signal Layer 2 w0.1: v1(17.85,82.85) 17.875,82.875 18.576,82.875 18.601,82.85 25.15,82.85 26.45,84.15 v1(56.075,84.15)
STMIPI_INT: TP28.1 U4.8 U5.17 | length 60.5
  Top Layer w0.1: TP28.1@12,80.95 16.225,80.95 v1(17.325,82.05) 17.35,82.025 19.625,82.025 U4.8@19.65,82.05 ; v1(57.175,84.525) 57.175,82.7 58.025,81.85 64.525,81.85 64.7,82.025 U5.17@65.775,82.025
  Signal Layer 2 w0.1: v1(17.325,82.05) 17.325,83 17.6,83.275 18.274,83.275 18.324,83.225 25.05,83.225 26.3,84.475 55.799,84.475 55.899,84.575 57.125,84.575 v1(57.175,84.525)
T_JTDI: R189.1 U12.L3 | length 50.5
  Top Layer w0.1: R189.1@84.75,23.518 91.767,23.518 93.649,25.4 94.675,25.4 v1(95.075,25) ; U12.L3@106.175,45.95 v2(106.5,45.625)
  Signal Layer 2 w0.1: v1(95.075,25) 96.25,25 97.106,24.144 100.706,24.144 101.775,23.075 106.2,23.075 106.822,22.453 v1(108.303,22.453)
  Bottom Layer w0.1: v2(106.5,45.625) 105.85,44.975 105.85,41.375 108.303,38.922 v1(108.303,22.453)
T_NRST: R88.1 U12.P3 | length 3
  Top Layer w0.1: R88.1@105.75,41.15 105.85,41.25 105.85,43.675 U12.P3@106.175,44
T_PWR_EN: TP47.1 U12.R5 | length 4.9
  Top Layer w0.1: U12.R5@107.475,43.35 107.475,39.525 TP47.1@108.25,38.75
T_PWR_EXT: R89.2 U12.R4 | length 2.3
  Top Layer w0.1: R89.2@106.825,41.15 106.925,41.25 106.925,43.216 106.825,43.316 U12.R4@106.825,43.35
T_SWCLK: R90.1 U12.A10 U12.M6 U12.M11 | length 17.3
  Top Layer w0.1: U12.M6@108.125,45.3 108.132,45.307 108.132,45.482 v1(108.45,45.8) ; U12.A10@110.725,52.45 110.754,52.479 110.754,52.604 v1(111.05,52.9) ; v1(111.5,45.8) 111.5,45.425 U12.M11@111.375,45.3 111.7,44.975 111.7,42.5 112.275,41.925 R90.1@112.275,41.15
  Bottom Layer w0.1: v1(108.45,45.8) 108.85,46.2 110.35,46.2 110.763,45.787 111.087,45.787 111.1,45.8 v1(111.5,45.8) 111.5,47.425 111.05,47.875 111.05,49.649 110.7,49.999 110.7,52.428 111.05,52.778 v1(111.05,52.9)
T_SWDIO: R81.1 U12.L2 U12.N12 | length 13.3
  Top Layer w0.1: R81.1@101.775,43.4 101.775,43.475 102.9,44.6 ; 102.901,44.6 103.15,44.849 ; 103.15,44.85 104,45.7 104.736,45.7 104.761,45.675 105.25,45.675 U12.L2@105.525,45.95 v2(105.85,45.625) ; U12.N12@112.025,44.65 v2(112.35,44.975)
  Bottom Layer w0.1: v2(105.85,45.625) 106.295,46.07 107.28,46.07 108.805,44.545 111.92,44.545 v2(112.35,44.975)
T_SWO: R61.1 U12.A6 U12.D12 | length 11.8
  Top Layer w0.1: U12.A6@108.125,52.45 108.125,52.757 108.375,53.007 v1(108.375,53.025) ; U12.D12@112.025,50.5 v2(112.35,50.825) 114.875,50.825 115.275,51.225 R61.1@116.85,51.225
  Bottom Layer w0.1: v1(108.375,53.025) 108.688,53.338 111.337,53.338 112.35,52.325 v2(112.35,50.825)
TAMP_BTN: B4.1 B4.2 R181.1 U14.U10 | length 56.5
  Top Layer w0.09: v2(72.4,33.075) 72.4,32.991 72.475,32.916 U14.U10@72.475,32.65
  Signal Layer 2 w0.1: v1(49.475,19.05) 51.1,20.675 71.075,20.675 71.625,21.225 72.8,21.225 v1(73.35,20.675)
  Bottom Layer w0.09: v2(72.4,33.075) 72.4,32.613 73,32.013 73,28.011 73.286,27.725 73.327,27.684 73.327,26.898 73.7,26.525
  Bottom Layer w0.1: v1(49.475,19.05) 49.475,17.284 48.025,15.834 R181.1@48.025,13.85 48.025,12.8 48.725,12.1 B4.2@50.975,12.1 B4.1@50.975,4.405 ; v1(73.35,20.675) 73.35,24.15 73.925,24.725 73.925,26.3 73.7,26.525
TD1_N: CN4.4 R92.1 U13.20 U15.4 | length 38.6
  Top Layer w0.09: CN4.4@25.2,36.45 23.205,36.45 22.945,36.19 22.945,36.123 22.892,36.07 22.784,36.07 22.152,36.07 21.665,35.583 21.665,33.717 21.891,33.491 22.142,33.24 34.208,33.24 35.03,34.062 35.03,37.35 35.18,37.5 U15.4@36.05,37.5 v1(36.05,36.825) ; R92.1@42.525,40.65 42.975,40.65 v1(43.413,40.213) 43.85,39.775 U13.20@44.375,39.775
  Bottom Layer w0.09: v1(36.05,36.825) 35.2,36.825 35.025,36.65 35.025,36.264 35.2,36.089 35.2,36.075 36.061,36.075 40.015,40.029 43.229,40.029 v1(43.413,40.213)
TD1_P: CN4.3 R95.1 U13.21 U15.3 | length 37.6
  Top Layer w0.09: CN4.3@25.2,35.43 23.205,35.43 22.945,35.69 22.945,35.757 22.892,35.81 22.676,35.81 22.26,35.81 21.925,35.475 21.925,33.825 22.25,33.5 34.1,33.5 34.77,34.17 34.77,37.35 34.62,37.5 U15.3@33.75,37.5 v1(33.75,36.825) ; R95.1@42.525,39.575 42.6,39.5 v1(43.425,39.5) 43.5,39.5 43.725,39.275 U13.21@44.375,39.275
  Bottom Layer w0.09: v1(33.75,36.825) 34.6,36.825 34.765,36.66 34.765,36.156 34.94,35.981 34.94,35.967 35.092,35.815 36.169,35.815 40.122,39.769 43.231,39.769 43.425,39.575 v1(43.425,39.5)
TD2_N: CN15.4 R37.1 U7.20 U8.4 | length 38.3
  Top Layer w0.09: CN15.4@25.2,58.98 23.205,58.98 22.945,58.72 22.945,58.653 22.892,58.6 22.784,58.6 21.882,58.6 21.49,58.208 21.49,56.392 21.741,56.141 22.192,55.69 33.208,55.69 34.855,57.337 34.855,59.7 35.005,59.85 U8.4@35.875,59.85 v1(35.875,59.175) ; R37.1@42.525,63.025 42.975,63.025 v1(43.413,62.588) 43.85,62.15 U7.20@44.375,62.15
  Bottom Layer w0.09: v1(35.875,59.175) 35,59.175 34.85,59.025 34.85,58.689 35.025,58.514 35.025,58.5 36.936,58.5 40.84,62.404 43.229,62.404 v1(43.413,62.588)
TD2_P: CN15.3 R39.1 U7.21 U8.3 | length 37.3
  Top Layer w0.09: CN15.3@25.2,57.96 23.205,57.96 22.945,58.22 22.945,58.287 22.892,58.34 22.676,58.34 21.99,58.34 21.75,58.1 21.75,56.5 22.3,55.95 33.1,55.95 34.595,57.445 34.595,59.7 34.445,59.85 U8.3@33.575,59.85 v1(33.575,59.175) ; R39.1@42.525,61.95 42.625,61.85 v1(43.425,61.85) 43.525,61.85 43.725,61.65 U7.21@44.375,61.65
  Bottom Layer w0.09: v1(33.575,59.175) 34.45,59.175 34.59,59.035 34.59,58.581 34.765,58.406 34.765,58.392 34.917,58.24 37.044,58.24 40.947,62.144 43.231,62.144 43.425,61.95 v1(43.425,61.85)
UART4_RX: R54.2 R72.1 U14.B5 | length 57.2
  Top Layer w0.075: v1(69.475,43.025) 69.475,43 69.89,42.585 69.89,40.272 69.975,40.187 U14.B5@69.975,40.15
  Top Layer w0.1: R72.1@94.525,45.125 94.525,46.45 v1(95.05,46.975) ; R54.2@108.425,55.75 v1(108.425,57)
  Signal Layer 2 w0.09: v1(69.475,43.025) 71.27,43.025 71.37,43.125
  Signal Layer 2 w0.1: 71.37,43.125 72.3,44.055 72.3,45.225 73.9,46.825 79.387,46.825 79.737,46.475 92.95,46.475 93.45,46.975 v1(95.05,46.975) ; v1(96.175,56.5) 103.825,56.5 104.275,56.95 105.94,56.95 106.215,57.225 108.141,57.225 108.366,57 v1(108.425,57)
  Bottom Layer w0.1: v1(95.05,46.975) 95.05,55.375 v1(96.175,56.5)
UART4_TX: R55.2 U14.D2 | length 76.7
  Top Layer w0.075: 65.175,42.992 65.8,42.367 65.8,40.325 67.221,38.904 68.079,38.904 68.325,39.15 U14.D2@68.475,39.15
  Top Layer w0.1: v1(62.8,59.875) 62.8,52.775 63.8,51.775 63.8,44.367 65.175,42.992 ; v1(111.7,57.725) 111.7,57.125 112.275,56.55 R55.2@112.275,55.75
  Signal Layer 2 w0.1: v1(62.8,59.875) 64.875,59.875 65.472,59.278 82.203,59.278 82.8,59.875 87.65,59.875 88.15,59.375 110.05,59.375 v1(111.7,57.725)
USART2_CTS: TP6.1 U1.5 U14.B2 | length 87.1
  Top Layer w0.075: 67.075,43.125 67.075,40.975 67.65,40.4 68.125,40.4 68.345,40.18 68.445,40.18 U14.B2@68.475,40.15
  Top Layer w0.1: v1(65.9,60.225) 65.85,60.175 65.85,49.45 67.078,48.222 67.078,43.426 67.075,43.423 67.075,43.125 ; v1(70.053,60.253) 70.053,61.55 85.878,77.375 v1(103.125,77.375) ; TP6.1@102.5,92.75 v1(103.375,92.75) 103.775,92.75 105.825,90.7 U1.5@105.825,90.025
  Signal Layer 2 w0.1: v1(65.9,60.225) v1@69.975,60.225
  Bottom Layer w0.1: v1(103.125,77.375) 103.125,80.75 102.8,81.075 102.8,84 103.375,84.575 v1(103.375,92.75)
USART2_RTS: TP3.1 U1.4 U14.C7 | length 86.4
  Top Layer w0.09: v2@70.975,39.15 v2(70.975,39.225) U14.C7@70.975,39.65
  Top Layer w0.1: v1(71.575,47.55) 71.925,47.9 71.925,52.375 71.55,52.75 71.55,62.05 86.075,76.575 104.25,76.575 v1(104.3,76.525) ; TP3.1@104,95 104,92.975 106.275,90.7 U1.4@106.275,90.025
  Bottom Layer w0.09: v2(70.975,39.225) 70.975,43.125
  Bottom Layer w0.1: 70.975,43.125 70.975,43.3 70.725,43.55 70.725,46.7 v1(71.575,47.55) ; v1(104,93.85) 104,88.976 103.95,88.926 103.95,88.574 104,88.524 104,87.476 103.95,87.426 103.95,87.074 104,87.024 104,84.45 103.9,84.35 103.9,76.925 v1(104.3,76.525)
USART2_RX: TP7.1 U1.3 U14.E9 | length 85.5
  Top Layer w0.09: v2(71.975,38.125) U14.E9@71.975,38.65
  Top Layer w0.1: v1(72.8,47.225) 72.8,47.624 72.825,47.649 72.825,48.001 72.825,56.774 72.775,56.824 72.775,57.176 72.8,57.201 72.8,62.15 85.825,75.175 ; 85.825,75.176 86.074,75.425 86.15,75.5 101.924,75.5 101.949,75.525 102.301,75.525 102.326,75.5 v1(107,75.5) ; TP7.1@105.5,92.75 106.725,91.525 U1.3@106.725,90.025
  Bottom Layer w0.075: 71.731,39.494 71.605,39.368 71.605,38.495 v2(71.975,38.125)
  Bottom Layer w0.09: 71.731,39.494 71.731,43.125
  Bottom Layer w0.1: 71.731,43.125 71.731,43.194 71.14,43.785 71.14,45.44 72.662,46.962 72.662,46.965 72.8,47.103 v1(72.8,47.225) ; v1(106.275,91.975) 106.95,91.3 106.95,75.55 v1(107,75.5)
USART2_TX: TP4.1 U1.2 U14.D3 | length 91.1
  Top Layer w0.09: U14.D3@68.975,39.15 v2(69.425,39.15) v2@69.45,39.15
  Top Layer w0.1: v1(68.775,45.275) 68.775,49.425 69.125,49.775 69.125,59.675 v1@69.05,59.75 ; v1(71.103,59.778) 71.103,62.122 71.1,62.125 85.9,76.925 104.099,76.925 104.124,76.95 107.375,76.95 v1(107.4,76.925) ; TP4.1@107,95 v1(107,93.7) 107,91.775 107.175,91.6 U1.2@107.175,90.025
  Signal Layer 2 w0.1: v1(69.078,59.703) 71.047,59.703 71.097,59.753 71.103,59.759 v1(71.103,59.778)
  Bottom Layer w0.09: 68.4,43.125 68.4,42.75 69.425,41.725 v2(69.425,39.15)
  Bottom Layer w0.1: 68.4,43.125 68.4,44.9 v1@68.725,45.225 ; v1(107,93.7) 107,91.825 107.3,91.525 107.3,90.35 108.025,89.625 108.025,88.225 107.4,87.6 v1(107.4,76.925)
USB1CN25_N: CN6.T2 U28.5 | length 3.9
  Top Layer w0.1: U28.5@96.85,16.7 96.85,16.525 96.925,16.45 96.926,16.45 96.985,16.391 96.985,15.79 97.885,14.89 97.885,14.515 CN6.T2@97,13.63
USB1CN25_P: CN6.T3 U28.6 | length 3.9
  Top Layer w0.1: U28.6@97.35,16.7 97.35,16.525 97.275,16.45 97.274,16.45 97.215,16.391 97.215,15.885 98.115,14.985 98.115,14.515 CN6.T3@99,13.63
USB2CN25_N: CN6.B2 U29.5 | length 8.3
  Top Layer w0.1: CN6.B2@97,11.01 97.885,11.895 97.885,12.294 98.091,12.5 99.65,12.5 100.075,12.925 100.075,14.85 99.31,15.615 99.31,16.391 99.251,16.45 99.25,16.45 99.175,16.525 U29.5@99.175,16.7
USB2CN25_P: CN6.B3 U29.6 | length 8.3
  Top Layer w0.1: CN6.B3@99,11.01 98.115,11.895 98.115,12.198 98.187,12.27 99.745,12.27 100.305,12.83 100.305,14.945 99.54,15.71 99.54,16.391 99.599,16.45 99.6,16.45 99.675,16.525 U29.6@99.675,16.7
USB3CN26_N: CN5.T2 U26.5 | length 3.9
  Top Layer w0.1: U26.5@77.85,16.7 77.85,16.525 77.925,16.45 77.926,16.45 77.985,16.391 77.985,15.79 78.885,14.89 78.885,14.515 CN5.T2@78,13.63
USB3CN26_P: CN5.T3 U26.6 | length 3.9
  Top Layer w0.1: U26.6@78.35,16.7 78.35,16.525 78.275,16.45 78.274,16.45 78.215,16.391 78.215,15.885 79.115,14.985 79.115,14.515 CN5.T3@80,13.63
USB4CN26_N: CN5.B2 U27.5 | length 8.3
  Top Layer w0.1: CN5.B2@78,11.01 78.885,11.895 78.885,12.294 79.091,12.5 80.65,12.5 81.075,12.925 81.075,14.85 80.31,15.615 80.31,16.391 80.251,16.45 80.25,16.45 80.175,16.525 U27.5@80.175,16.7
USB4CN26_P: CN5.B3 U27.6 | length 8.3
  Top Layer w0.1: CN5.B3@80,11.01 79.115,11.895 79.115,12.198 79.187,12.27 80.745,12.27 81.305,12.83 81.305,14.945 80.54,15.71 80.54,16.391 80.599,16.45 80.6,16.45 80.675,16.525 U27.6@80.675,16.7
USB_D1_N: U14.AA16 U33.30 | length 40
  Top Layer w0.09: U14.AA16@75.474,30.65 75.475,28.789 76.405,27.859 76.405,27.725 76.4,27.72
  Top Layer w0.1: U33.30@59.15,11.75 59.9,11.75 v1(60.05,11.6) ; v1(68.113,11.238) 68.114,11.238 68.385,11.508 68.385,11.591 68.385,21.16 69.075,21.85 75.825,21.85 76.4,22.425 76.4,27.72
  Bottom Layer w0.1: v1(60.05,11.6) 60.05,11.681 60.161,11.792 60.161,11.826 60.22,11.885 60.303,11.885 60.88,11.885 61.12,12.125 61.12,13.095 61.52,13.495 67.88,13.495 68.385,12.99 68.385,11.512 68.385,11.429 68.194,11.238 v1(68.113,11.238)
USB_D1_P: U14.Y16 U33.31 | length 41
  Top Layer w0.09: U14.Y16@75.474,31.15 75.491,31.134 75.491,30.993 75.728,30.755 75.728,30.545 75.695,30.511 75.695,28.88 76.625,27.95 76.625,27.725 76.63,27.72
  Top Layer w0.1: U33.31@59.15,12.25 59.9,12.25 v1(60.05,12.4) ; v1(68.888,11.238) v1(68.888,11.238) 68.615,11.508 68.615,11.687 68.615,21.065 69.17,21.62 75.92,21.62 76.63,22.33 76.63,27.72
  Bottom Layer w0.1: v1(60.05,12.4) 60.05,12.319 60.161,12.208 60.161,12.174 60.22,12.115 60.398,12.115 60.785,12.115 60.89,12.22 60.89,13.191 61.425,13.725 67.975,13.725 68.615,13.085 68.615,11.607 68.615,11.429 68.806,11.238 v1(68.888,11.238)
USB_D2_N: U14.Y13 U32.2 | length 56.1
  Top Layer w0.075: U14.Y13@73.975,31.15 73.986,31.139 73.986,30.987 74.221,30.752 74.221,30.548 74.18,30.507 74.18,29.295 74.4,29.075 74.4,27.725
  Top Layer w0.1: 74.395,27.725 74.395,24.772 74.413,24.755 74.413,24.438 74.753,24.098 74.753,23.623 v1(75.025,23.35) ; v1(114.05,16.75) 114.25,16.55 U32.2@114.25,16
  Bottom Layer w0.1: v1(75.025,23.35) 74.998,23.35 74.752,23.596 74.752,23.679 74.753,24.253 75.05,24.55 75.875,24.55 76.35,24.075 76.35,23.3 78.255,21.395 113.755,21.395 114.385,20.765 114.385,17.41 114.385,17.085 v1(114.05,16.75)
USB_D2_P: U14.AA13 U32.1 | length 56.2
  Top Layer w0.075: U14.AA13@73.975,30.65 73.975,29.491 73.975,29.193 74.17,28.997 74.187,28.98 74.187,27.836 74.165,27.813 74.165,27.725
  Top Layer w0.1: 74.165,27.725 74.165,24.677 74.183,24.659 74.183,24.342 74.523,24.003 74.523,23.623 v1(74.25,23.35) ; U32.1@114.75,16 114.75,16.55 v1(114.95,16.75)
  Bottom Layer w0.1: v1(74.25,23.35) 74.277,23.35 74.523,23.596 74.523,23.774 74.523,24.348 74.955,24.78 75.97,24.78 76.58,24.17 76.58,23.395 78.35,21.625 113.85,21.625 114.615,20.86 114.615,17.505 114.615,17.085 v1(114.95,16.75)
USB_DCONN_N: CN7.A7 CN7.B7 U32.5 | length 18.1
  Top Layer w0.1: U32.5@114.25,14.7 114.25,14.525 114.325,14.45 114.326,14.45 114.395,14.381 114.395,14.098 114.147,13.85 v1(114.025,13.85) 114.373,13.502 114.373,13.127 114.373,11.728 114.61,11.49 114.61,8.735 114.61,6.57 114.475,6.435 CN7.B7@114.475,6.235 ; CN7.A7@115.225,7.935 v1@115.225,8.85
  Bottom Layer w0.1: v1(114.025,13.85) 114.111,13.936 114.288,13.936 114.373,14.021 114.373,14.104 114.373,14.271 114.206,14.437 113.587,14.437 113.45,14.3 113.45,13.45 114.84,12.06 114.84,11.123 114.84,9.23 114.84,9 114.959,8.881 115.294,8.881 v1(115.325,8.85)
USB_DCONN_P: CN7.A6 CN7.B6 U32.6 | length 18.8
  Top Layer w0.1: CN7.A6@114.225,7.935 v1@114.225,8.85 ; U32.6@114.75,14.7 114.75,14.525 114.625,14.4 114.625,14.053 114.828,13.85 v1(114.95,13.85) 114.603,13.503 114.603,13.032 114.603,11.823 114.84,11.585 114.84,8.83 114.84,6.57 114.975,6.435 CN7.B6@114.975,6.235
  Bottom Layer w0.1: v1(114.125,8.85) 114.156,8.881 114.491,8.881 114.61,9 114.61,11.218 114.61,11.965 113.22,13.355 113.22,14.395 113.492,14.667 114.302,14.667 114.603,14.367 114.603,14.199 114.603,14.021 114.687,13.936 114.864,13.936 v1(114.95,13.85)
USB_DEV_HS_CN_N: CN10.2 U18.5 | length 6.2
  Top Layer w0.1: U18.5@119.825,34.325 120.375,34.325 v1(120.575,34.125)
  Bottom Layer w0.1: v1(120.575,34.125) 120.575,34.135 120.24,34.47 119.93,34.47 119.67,34.73 119.67,35.47 120.065,35.865 122.166,35.865 122.225,35.924 122.225,35.925 122.375,36.075 CN10.2@122.85,36.075
USB_DEV_HS_CN_P: CN10.3 U18.6 | length 5.4
  Top Layer w0.1: U18.6@119.825,34.825 120.375,34.825 v1(120.575,35.025)
  Bottom Layer w0.1: v1(120.575,35.025) 120.575,35.015 120.26,34.7 120.025,34.7 119.9,34.825 119.9,35.375 120.16,35.635 122.166,35.635 122.225,35.576 122.225,35.575 122.375,35.425 CN10.3@122.85,35.425
USB_DEV_HS_N: U12.R14 U18.2 | length 11.6
  Top Layer w0.1: U12.R14@113.325,43.35 113.354,43.321 113.447,43.321 113.535,43.233 113.535,43.15 113.535,42.59 117.3,38.825 117.3,34.875 117.715,34.46 118.075,34.46 118.216,34.46 118.275,34.401 118.275,34.4 118.35,34.325 U18.2@118.525,34.325
USB_DEV_HS_P: U12.R15 U18.1 | length 11.2
  Top Layer w0.1: U12.R15@113.975,43.35 113.946,43.321 113.853,43.321 113.765,43.233 113.765,43.055 113.765,42.685 117.53,38.92 117.53,34.97 117.81,34.69 117.98,34.69 118.216,34.69 118.275,34.749 118.275,34.75 118.35,34.825 U18.1@118.525,34.825
USB_PWR_CC1: R149.2 U14.AA4 | length 68.6
  Top Layer w0.075: v1(68.1,28.1) 68.1,28.375 68.125,28.4 69.475,29.75 U14.AA4@69.475,30.65
  Top Layer w0.1: v1(17.445,17.089) R149.2@18.27,17.089
  Signal Layer 2 w0.09: 65.175,27.975 68.102,27.975 68.1,27.977 v1(68.1,28.1)
  Signal Layer 2 w0.1: v1(18.925,29.2) 23.8,29.2 24.425,28.575 31.249,28.575 31.324,28.5 31.676,28.5 31.751,28.575 37.2,28.575 38.175,29.55 39.229,29.55 39.503,29.276 41.589,29.276 43.516,27.35 44.227,27.35 44.474,27.597 46.303,27.597 47.15,26.75 58.891,26.75 58.966,26.675 60.899,26.675 62.199,27.975 65.175,27.975
  Bottom Layer w0.1: v1(17.445,17.089) 18.925,18.57 v1(18.925,29.2)
USB_PWR_CC2: R144.2 U14.W9 | length 70.7
  Top Layer w0.075: v2(70.475,27.65) 70.494,27.65 70.569,27.725 70.763,27.919 71.133,27.919 71.801,28.586 71.801,28.988 71.728,29.061 71.728,31.403 U14.W9@71.975,31.65
  Top Layer w0.1: v1(17.42,20.614) R144.2@18.27,20.614
  Signal Layer 2 w0.1: v1(17.42,20.614) 25.605,20.614 28.545,17.675 38.775,17.675 39.225,18.125 39.65,18.125 40.148,17.627 41.401,17.627 41.525,17.751 41.825,18.051 42.159,18.051 42.442,18.334 42.442,18.337 42.681,18.575 49.75,18.575 51.35,20.175 71.375,20.175 v1(71.925,20.725)
  Bottom Layer w0.1: v2(70.475,27.65) 70.475,25.275 71.275,24.475 71.275,21.375 v1(71.925,20.725)
USBC_EN: TP56.1 U20.20 U21.22 | length 25.3
  Top Layer w0.1: TP56.1@96.075,26.1 v1(97.225,24.95) U21.22@99.075,24.95 ; U20.20@115.825,24.4 116.5,24.4 116.825,24.725 v1(116.825,25.325)
  Signal Layer 2 w0.1: v1(97.225,24.95) 99.675,24.95 100.425,25.7 112.149,25.7 112.174,25.725 112.526,25.725 112.551,25.7 116.45,25.7 v1(116.825,25.325)
USBC_INTn: TP51.1 U20.19 U21.17 | length 25.8
  Top Layer w0.1: TP51.1@101.3,30.15 101.3,29.025 v1(101.575,28.75) U21.17@101.575,25.325 ; U20.19@115.825,23.9 v1(116.75,23.9)
  Signal Layer 2 w0.1: v1(101.575,28.75) 101.65,28.825 116.35,28.825 v1(116.425,28.75)
  Bottom Layer w0.1: v1(116.425,28.75) 116.35,28.675 116.35,24.3 v1(116.75,23.9)
USBDN1_N: U28.2 U33.1 | length 43.1
  Top Layer w0.1: U33.1@58.4,15.5 58.4,16.25 v1(58.55,16.4) ; v1(96.65,18.75) 96.85,18.55 U28.2@96.85,18
  Bottom Layer w0.1: v1(58.55,16.4) 58.498,16.4 58.265,16.633 58.265,16.716 58.265,17.19 58.47,17.395 63.795,17.395 64.32,17.92 74.97,17.92 76.425,19.375 96.775,19.375 96.985,19.165 96.985,18.978 96.757,18.75 v1(96.65,18.75)
USBDN1_P: U28.1 U33.2 | length 43.8
  Top Layer w0.1: v1(57.75,16.4) 57.9,16.25 U33.2@57.9,15.5 ; U28.1@97.35,18 97.35,18.55 v1(97.55,18.75)
  Bottom Layer w0.1: v1(57.75,16.4) 57.802,16.4 58.035,16.633 58.035,16.811 58.035,17.285 58.375,17.625 63.7,17.625 64.225,18.15 74.875,18.15 76.33,19.605 96.87,19.605 97.215,19.26 97.215,18.978 97.443,18.75 v1(97.55,18.75)
USBDN2_N: U29.2 U33.3 | length 48.1
  Top Layer w0.1: U33.3@57.4,15.5 57.325,15.575 57.325,16.775 57.575,17.025 v1(57.575,17.075) ; v1(98.975,18.75) 99.175,18.55 U29.2@99.175,18
  Bottom Layer w0.1: v1(57.575,17.075) 57.473,17.075 57.265,17.283 57.265,17.366 57.265,17.865 57.92,18.52 63.82,18.52 64.445,19.145 74.895,19.145 76.025,20.275 98.975,20.275 99.31,19.94 99.31,19.016 99.31,18.933 99.251,18.875 99.221,18.875 99.097,18.75 v1(98.975,18.75)
USBDN2_P: U29.1 U33.4 | length 48.8
  Top Layer w0.1: v1(56.725,17.075) 56.725,17.025 56.9,16.85 U33.4@56.9,15.5 ; U29.1@99.675,18 99.675,18.55 v1(99.875,18.75)
  Bottom Layer w0.1: v1(56.725,17.075) 56.827,17.075 57.035,17.283 57.035,17.461 57.035,17.96 57.825,18.75 63.725,18.75 64.35,19.375 74.8,19.375 75.93,20.505 99.07,20.505 99.54,20.035 99.54,19.111 99.54,18.933 99.599,18.875 99.629,18.875 99.753,18.75 v1(99.875,18.75)
USBDN3_N: U26.2 U33.6 | length 26.7
  Top Layer w0.1: U33.6@55.9,15.5 55.9,16.25 56,16.35 v1(56,16.4) ; v1(77.65,18.75) 77.85,18.55 U26.2@77.85,18
  Bottom Layer w0.1: v1(56,16.4) 56,16.352 55.765,16.117 55.765,16.034 55.765,15.925 55.915,15.775 62.925,15.775 64.65,17.5 77.8,17.5 77.985,17.685 77.985,18.484 77.985,18.567 77.926,18.625 77.896,18.625 77.772,18.75 v1(77.65,18.75)
USBDN3_P: U26.1 U33.7 | length 27.4
  Top Layer w0.1: v1(55.3,16.375) 55.3,16.35 55.4,16.25 U33.7@55.4,15.5 ; U26.1@78.35,18 78.35,18.55 v1(78.55,18.75)
  Bottom Layer w0.1: v1(55.3,16.375) 55.3,16.327 55.535,16.092 55.535,15.939 55.535,15.83 55.82,15.545 63.02,15.545 64.745,17.27 77.895,17.27 78.215,17.59 78.215,18.389 78.215,18.567 78.274,18.625 78.304,18.625 78.428,18.75 v1(78.55,18.75)
USBDN4_N: U27.2 U33.8 | length 32.7
  Top Layer w0.1: U33.8@54.9,15.5 54.83,15.57 54.83,16.78 v1(55.125,17.075) ; v1(79.975,18.75) 80.175,18.55 U27.2@80.175,18
  Bottom Layer w0.1: v1(55.125,17.075) 54.765,16.715 54.765,16.565 54.765,15.585 55.275,15.075 63.399,15.075 64.979,16.655 80.08,16.655 80.31,16.885 80.31,18.227 80.31,18.415 v1(79.975,18.75)
USBDN4_P: U27.1 U33.9 | length 33.4
  Top Layer w0.1: v1(54.175,17.075) 54.4,16.85 U33.9@54.4,15.5 ; U27.1@80.675,18 80.675,18.55 v1(80.875,18.75)
  Bottom Layer w0.1: v1(54.175,17.075) 54.535,16.715 54.535,16.47 54.535,15.49 55.18,14.845 63.494,14.845 65.074,16.425 80.175,16.425 80.54,16.79 80.54,18.132 80.54,18.415 v1(80.875,18.75)
uSD_DETECT: CN3.9 R46.2 R188.1 U10.1 | length 60.5
  Top Layer w0.1: R188.1@84.75,24.568 92.518,24.568 94.875,26.925 97.65,26.925 v1(98.45,26.125) ; v1(101.425,58.95) R46.2@109.9,58.95 109.913,58.937 U10.1@110.875,58.937 110.888,58.95 CN3.9@112.5,58.95
  Bottom Layer w0.1: v1(98.45,26.125) 99.074,26.125 99.249,26.3 99.525,26.575 99.525,28.825 101.425,30.725 v1(101.425,58.95)
VBUS_MEAS: R129.1 R134.2 U21.13 | length 3.4
  Top Layer w0.1: U21.13@102.95,24.45 R129.1@104.925,24.45 R134.2@104.925,23.025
